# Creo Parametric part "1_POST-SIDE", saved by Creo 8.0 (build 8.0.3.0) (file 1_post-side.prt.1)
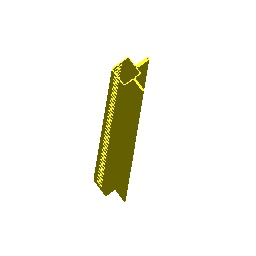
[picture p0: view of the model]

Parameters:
  SMT_DFLT_BEND_REL_LENGTH_TYPE = "Through All"

Other parameters: SMT_UPDATE_BEND_ALLOW_INFO, SMT_THICKNESS, SMT_PART_BEND_ALLOWANCE_FACTOR, SMT_DFLT_BEND_RADIUS, SMT_DFLT_BEND_ANGLE, SMT_DFLT_CRNR_REL_WIDTH, SMT_DFLT_CRNR_REL_DEPTH, SMT_DFLT_BEND_REL_WIDTH, SMT_DFLT_BEND_REL_DEPTH, SMT_DFLT_BEND_REL_LENGTH, SMT_DFLT_BEND_REL_ANGLE, SMT_GAP, SMT_DFLT_EDGE_TREA_WIDTH, SMT_DFLT_MITER_CUT_WIDTH, SMT_DFLT_MITER_CUT_OFFSET

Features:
  1. datum plane "RIGHT"
  2. datum plane "TOP"
  3. datum plane "FRONT"
  4. coordinate system
  5. pattern
  6. cut
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
Layers: 0_ALL_AXES, 0_ALL_AXIS, 0_ALL_CSYS, 0_ALL_CURVES, 0_ALL_PLANES, 0_ALL_POINTS, 0_ALL_SURFS, POST-SIDE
